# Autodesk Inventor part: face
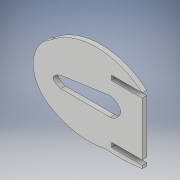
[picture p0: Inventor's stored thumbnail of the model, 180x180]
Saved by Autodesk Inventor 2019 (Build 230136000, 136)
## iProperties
Created: 2020-02
Part Number: face
Material: Generic
Document SubType Name: Modeling
Designer: shivu
Density: 1 g/cm^3
Appearance: Default
Author: shivu
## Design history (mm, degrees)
sketch "Sketch1"
  geometry: L1 (25, 0)-(45, 0); L2 (45, 0)-(45, -35.06); L3 (45, -35.06)-(25, -35.06); L4 (45, 0)-(25, 0); L5 (25, 0)-(25, 3); L6 (25, -35.06)-(25, -38.06); L7 (25, -38.06)-(45, -38.06); L8 (25, 3)-(45, 3); L9 (45, -38.06)-(45, -40.06); L10 (-7.977, -13.655)-(23.705, -9.179); L11 (-8.274, -21.307)-(24.352, -21.307); A1 r 46.643 centre (15.072, -32.775) between (45, 3) and (-14.856, 3); A2 r 21.571 centre (-4.699, -16.03) between (-14.856, 3) and (-16.09, -34.348); A3 r 50.191 centre (10.413, 8.274) between (-16.09, -34.348) and (20.823, -40.825); A4 r 105.967 centre (29.581, 64.779) between (20.823, -40.825) and (45, -40.06); A5 r 8.212 centre (23.368, -17.385) between (31.088, -14.585) and (23.705, -9.179); A6 r 7.953 centre (23.219, -13.435) between (24.352, -21.307) and (31.088, -14.585); 2 further points; 1 other entity
  constraints: 22 end point, 12 point on circle, 6 centre point, 4 horizontal, 2 perpendicular, 2 vertical, 1 parallel, 1 point on line, 1 tangent, 4 other
  dimensions: "d24" = 20 distance of L5.end L8.end; "d25" = 20 distance of L6.end L7.end; "d26" = 2 distance of L7.end L9.end
extrude "Extrusion1" new body sketch "Sketch1" distance "d11" = 2; taper "d12" = 0 deg
extrude "Extrusion2" join sketch "Sketch1" distance "d22" = 3; taper "d23" = 0 deg
extrude "Extrusion3" join sketch "Sketch1" distance "d27" = 3; taper "d28" = 0 deg
extrude "Extrusion4" join sketch "Sketch1" distance "d29" = 3; taper "d30" = 0 deg
body "Solid1"
